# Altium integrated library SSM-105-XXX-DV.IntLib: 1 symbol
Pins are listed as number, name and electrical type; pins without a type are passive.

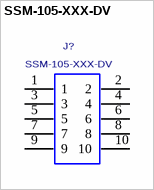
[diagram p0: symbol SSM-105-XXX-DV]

## SSM-105-XXX-DV
designator J?
Socket Strip, Surface Mount, Double Row ,0.100" Pitch, 10 PINS.; MANUFACTURER: SAMTEC
footprint SSM-105-XXX-DV
pins: 1, 2, 3, 4, 5, 6, 7, 8, 9, 10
